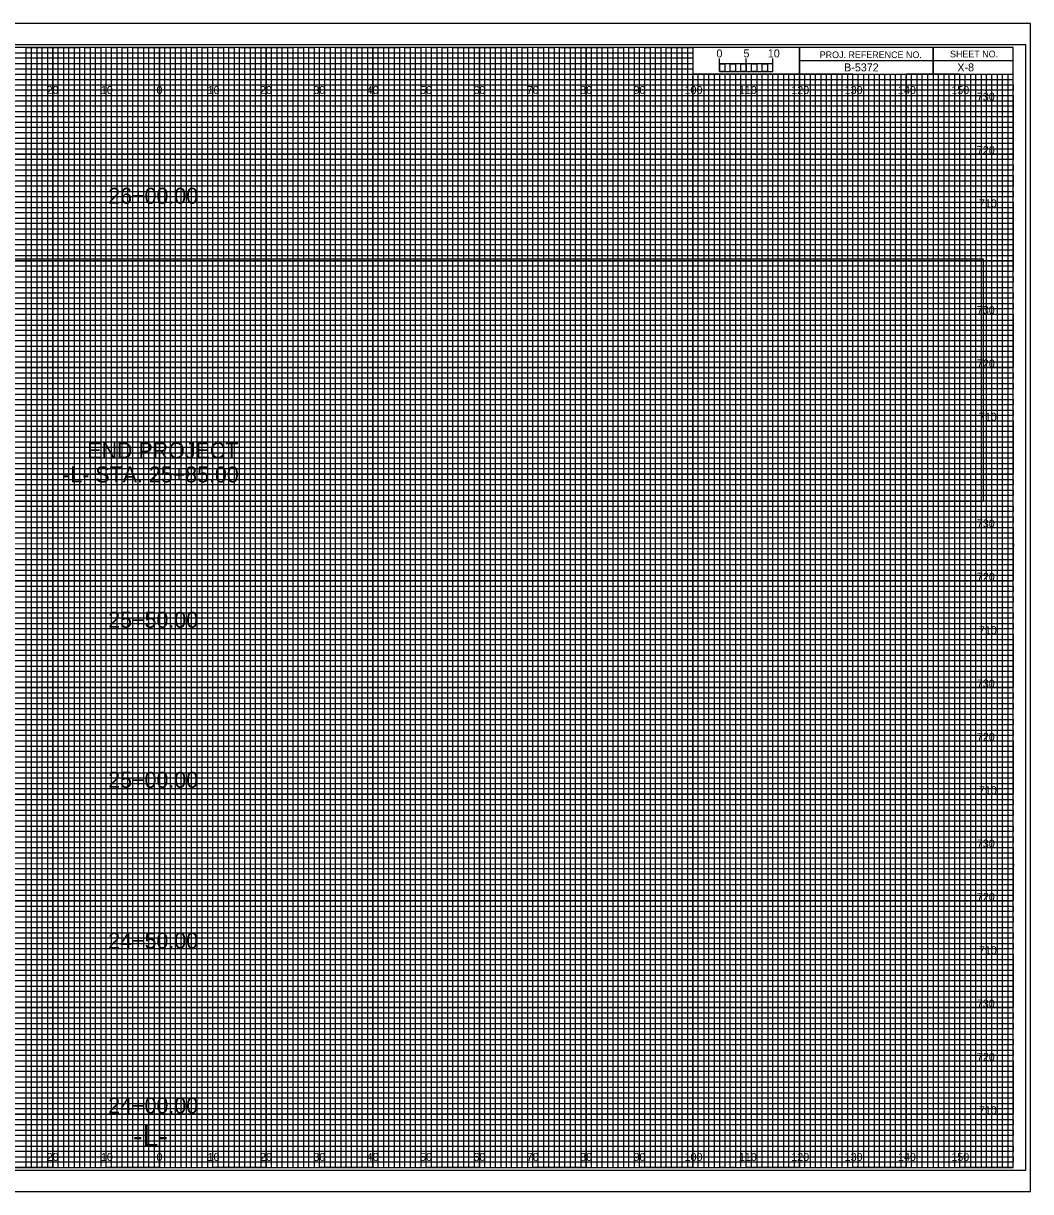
# Model space of a CAD drawing. Extents: x -98 to 717, y -10 to 1974.
# Drawn here: x 134.5 to 323.3, y 1535.5 to 1754.5 of the extents above; entities that cross this region are included whole.
import ezdxf

# ---------------------------------------------------------------- set-up
doc = ezdxf.new("R2010")
doc.units = 0
for name, color, linetype in [('Default', 7, 'Continuous'), ('Exist XS Center Line Elevation Label', 7, 'Continuous'), ('Prop CMT Conc Surface', 7, 'Continuous'), ('Prop CMT Concrete Structures', 7, 'Continuous'), ('Prop CMT Pvmt Course 1', 7, 'Continuous'), ('Prop CMT Pvmt Course 1 CG', 7, 'Continuous'), ('Prop CMT Pvmt Course 2', 7, 'Continuous'), ('Prop CMT Pvmt Course 3', 7, 'Continuous'), ('Prop CMT Pvmt Surface', 7, 'Continuous'), ('Prop CMT Pvmt Surface Shoulder', 7, 'Continuous'), ('Prop CMT Shld Paved Course 1', 7, 'Continuous'), ('Prop CMT Shld Paved Course 2', 7, 'Continuous'), ('Prop CMT Shld Paved Course 3', 7, 'Continuous'), ('Prop CMT Slope Grass', 7, 'Continuous'), ('Prop CMT Subgrade Earthwork', 7, 'Continuous'), ('Prop XS Ditch Standard Text', 7, 'Continuous'), ('Prop XS Earthwork Shape', 7, 'Continuous'), ('Prop XS Elevation Labels', 7, 'Continuous'), ('Typical Curb CELL', 7, 'Continuous')]:
    doc.layers.add(name, color=color, linetype=linetype)

msp = doc.modelspace()

# ---------------------------------------------------------------- linework, layer by layer
at = {"layer": 'Default'}
msp.add_lwpolyline([(-13.4, 1535.5), (323.3, 1535.5), (323.3, 1754.5), (-13.4, 1754.5)], close=True, dxfattribs=at)
at = {"layer": 'Exist XS Center Line Elevation Label'}
for p, q in [((0, 1749), (260, 1749)), ((260, 1747.98), (0, 1747.98)), ((260, 1749), (260, 1747.98)), ((0, 1747), (260, 1747)), ((260, 1745.89), (0, 1745.89)), ((260, 1747), (260, 1745.89)), ((0, 1744), (320, 1744))]:
    msp.add_line(p, q, dxfattribs=at)
for points in [[(0, 1743), (270, 1743), (320, 1743), (320, 1742), (0, 1742)], [(0, 1741), (320, 1741), (320, 1739), (0, 1739)], [(0, 1738), (320, 1738), (320, 1737), (0, 1736.98)], [(0, 1736), (320, 1736), (320, 1734), (0, 1734)], [(0, 1733), (320, 1733), (320, 1732), (0, 1732)], [(0, 1731), (320, 1731), (320, 1729), (0, 1729)], [(0, 1728), (320, 1728), (320, 1727), (0, 1727)], [(0, 1726), (320, 1726), (320, 1724), (0, 1724)], [(0, 1723), (320, 1723), (320, 1722), (0, 1722)], [(0, 1721), (320, 1721), (320, 1719), (0, 1719)], [(0, 1718), (320, 1718), (320, 1717), (0, 1717)], [(0, 1716), (320, 1716), (320, 1713.95), (320, 1713), (320, 1712), (0, 1712)], [(0, 1714), (320, 1714), (320, 1713), (0, 1713)], [(0, 1711), (320, 1711), (320, 1709), (0, 1709.03)], [(0, 1709.03), (320, 1709), (320, 1708), (0, 1708)], [(0, 1707), (320, 1707), (320, 1706), (0, 1706)], [(0, 1704), (320, 1704), (320, 1703), (0, 1703)], [(0, 1702), (320, 1702), (320, 1701), (0, 1701)], [(-0.07, 1698.89), (320, 1698.89), (320, 1697.88), (-0.07, 1697.88)], [(0, 1697), (320, 1697), (320, 1696), (0, 1696)], [(0, 1694), (320, 1694), (320, 1693), (0, 1693)], [(0, 1692), (320, 1692), (320, 1691), (0, 1691)], [(0, 1689), (320, 1689), (320, 1688), (0, 1688)], [(0, 1687), (320, 1687), (320, 1686), (0, 1686)], [(0, 1684), (320, 1684), (320, 1683), (0, 1683)], [(0, 1682), (320, 1682), (320, 1681), (0, 1681)], [(0, 1679), (320, 1679), (319.99, 1677.98), (0, 1678)], [(0, 1677), (320, 1677), (320, 1676), (0, 1676)], [(0, 1674), (320, 1674), (320, 1673), (0, 1673)], [(0, 1672), (320, 1672), (320, 1671), (0, 1671)], [(0, 1669), (320, 1669), (320, 1668), (0, 1668)], [(0, 1667), (320, 1667), (320, 1666), (0, 1666)], [(0, 1664), (320, 1664), (320, 1663), (0, 1663)], [(0, 1662), (320, 1662), (320, 1661), (0, 1661)], [(0, 1659), (320, 1659), (320, 1658), (0, 1658)], [(0, 1656.99), (320.07, 1656.91), (320, 1656), (0, 1656)], [(0, 1654), (320, 1654), (320, 1653), (0, 1653)], [(0, 1652), (320, 1652), (320, 1651), (0, 1651)], [(0, 1649), (320, 1649), (320, 1648), (0, 1648)], [(0, 1647), (320, 1647), (320, 1646), (0, 1646)], [(0, 1644), (320, 1644), (320, 1643), (0, 1643)], [(0, 1642), (320, 1642), (320, 1641), (0, 1641)], [(0, 1639), (320, 1639), (320, 1638), (0, 1638)], [(0, 1637), (320, 1637), (320, 1636), (0, 1636)], [(0, 1634), (320, 1634), (320, 1633), (0, 1633)], [(0, 1632), (320, 1632), (320, 1631), (0, 1631)], [(0, 1629), (320, 1629), (320, 1628), (0, 1628)], [(0, 1627), (320, 1627), (320, 1626), (0, 1626)], [(0, 1624), (320, 1624), (320, 1623), (0, 1623)], [(0, 1622), (320, 1622), (320, 1621), (0, 1621)], [(0, 1619), (320, 1619), (319.99, 1617.98), (0, 1618)], [(0, 1617), (320, 1617), (320, 1616), (0, 1616)], [(0, 1614), (320, 1614), (320, 1613), (0, 1613)], [(0, 1612), (320, 1612), (320, 1611), (0, 1611)], [(0, 1609), (320, 1609), (320, 1608), (0, 1608)], [(0, 1607), (320, 1607), (320, 1606), (0, 1606)], [(0, 1604), (320, 1604), (320, 1603), (0, 1603)], [(0, 1602), (320, 1602), (320, 1601), (0, 1601)], [(0, 1599), (320, 1599), (320, 1598), (0, 1598)], [(0, 1596.99), (320.07, 1596.91), (320, 1596), (0, 1596)], [(0, 1594), (320, 1594), (320, 1593), (0, 1593)], [(0, 1592), (320, 1592), (320, 1591), (0, 1591)], [(0, 1589), (320, 1589), (320, 1588), (0, 1588)], [(0, 1587), (320, 1587), (320, 1586), (0, 1586)], [(0, 1584), (320, 1584), (320, 1583), (0, 1583)], [(0, 1582), (320, 1582), (320, 1581), (0, 1581)], [(0, 1579), (320, 1579), (320, 1578), (0, 1578)], [(0, 1577), (320, 1577), (320, 1576), (0, 1576)], [(0, 1574), (320, 1574), (320, 1573), (0, 1573)], [(0, 1572), (320, 1572), (320, 1571), (0, 1571)], [(0, 1569), (320, 1569), (320, 1568), (0, 1568)], [(0, 1567), (320, 1567), (320, 1566), (0, 1566)], [(0, 1564), (320, 1564), (320, 1563), (0, 1563)], [(0, 1562), (320, 1562), (320, 1561), (0, 1561)], [(0, 1559), (320, 1559), (320, 1558), (0, 1558)], [(0, 1557), (320, 1557), (320, 1556), (0, 1556)], [(0, 1554), (320, 1554), (320, 1553), (0, 1553)], [(0, 1552), (320, 1552), (320, 1551), (0, 1551)], [(0, 1549), (320, 1549), (320, 1548), (0, 1548)], [(0, 1547), (320, 1547), (320, 1546), (0, 1546)], [(0, 1544), (320, 1544), (320, 1543), (0, 1543)], [(0, 1542), (320, 1542), (320, 1541), (0, 1541)]]:
    msp.add_lwpolyline(points, dxfattribs=at)
at = {"layer": 'Prop CMT Conc Surface'}
for p, q in [((305, 1750), (305, 1745)), ((305, 1745), (305, 1750)), ((280, 1747.5), (280, 1745)), ((320, 1747.49), (280, 1747.49)), ((280, 1745), (320, 1745))]:
    msp.add_line(p, q, dxfattribs=at)
for points in [[(320, 1750), (0, 1750), (0, 1540), (320, 1540)], [(280, 1750), (260, 1750), (260, 1745.03), (280, 1745.03)], [(320, 1750), (280, 1750), (280, 1745), (320, 1745)]]:
    msp.add_lwpolyline(points, close=True, dxfattribs=at)
at = {"layer": 'Prop CMT Concrete Structures'}
for p, q in [((140, 1540), (140, 1750)), ((150, 1540), (150, 1750)), ((160, 1540), (160, 1750)), ((170, 1540), (170, 1750)), ((180, 1540), (180, 1750)), ((190, 1540), (190, 1750)), ((200, 1540), (200, 1750)), ((210, 1540), (210, 1750)), ((220, 1540), (220, 1750)), ((230, 1540), (230, 1750)), ((240, 1540), (240, 1750)), ((250, 1540), (250, 1750)), ((260, 1540), (260, 1744.69)), ((270, 1540), (270, 1744.69)), ((280, 1540), (280, 1744.69)), ((290, 1540), (290, 1744.69)), ((300, 1540), (300, 1744.69)), ((310, 1540), (310, 1744.69)), ((0, 1740), (320, 1740)), ((0, 1730), (320, 1730)), ((0, 1720), (320, 1720)), ((0, 1710), (320, 1710)), ((0, 1700), (320, 1700)), ((0, 1690), (320, 1690)), ((0, 1680), (320, 1680)), ((0, 1670), (320, 1670)), ((0, 1660), (320, 1660)), ((0, 1650), (320, 1650)), ((0, 1640), (320, 1640)), ((0, 1630), (320, 1630)), ((0, 1620), (320, 1620)), ((0, 1610), (320, 1610)), ((0, 1600), (320, 1600)), ((0, 1590), (320, 1590)), ((0, 1580), (320, 1580)), ((0, 1570), (320, 1570)), ((0, 1560), (320, 1560)), ((0, 1550), (320, 1550))]:
    msp.add_line(p, q, dxfattribs=at)
at = {"layer": 'Prop CMT Pvmt Course 2'}
msp.add_lwpolyline([(-13.4, 1535.5), (323.3, 1535.5), (323.3, 1754.5), (-13.4, 1754.5)], close=True, dxfattribs=at)
at = {"layer": 'Prop CMT Pvmt Course 3'}
msp.add_lwpolyline([(-10.8, 1539.5), (322.4, 1539.5), (322.4, 1750.5), (-10.8, 1750.5)], close=True, dxfattribs=at)
at = {"layer": 'Prop CMT Pvmt Surface'}
for p, q in [((323.3, 1754.5), (-13.4, 1754.5)), ((-13.4, 1535.5), (323.3, 1535.5))]:
    msp.add_line(p, q, dxfattribs=at)
at = {"layer": 'Prop CMT Slope Grass'}
for p, q in [((265, 1745.49), (265, 1747.9)), ((265, 1746.9), (265, 1747.9)), ((270, 1745.49), (270, 1747.9)), ((275, 1745.49), (275, 1747.9)), ((275, 1746.9), (275, 1747.9))]:
    msp.add_line(p, q, dxfattribs=at)
for points in [[(275, 1746.9), (265, 1746.9), (265, 1745.49), (275, 1745.49)], [(265, 1746.9), (266, 1746.9), (266, 1745.49), (265, 1745.49)], [(267, 1746.9), (268, 1746.9), (268, 1745.49), (267, 1745.49)], [(269, 1746.9), (270, 1746.9), (270, 1745.49), (269, 1745.49)], [(271, 1746.9), (272, 1746.9), (272, 1745.49), (271, 1745.49)], [(273, 1746.9), (274, 1746.9), (274, 1745.49), (273, 1745.49)]]:
    msp.add_lwpolyline(points, close=True, dxfattribs=at)
at = {"layer": 'Prop CMT Subgrade Earthwork'}
for p, q in [((267, 1745), (266.01, 1745)), ((266.01, 1745), (266.01, 1540)), ((267, 1540), (267, 1745)), ((269, 1745), (268, 1745)), ((268, 1745), (268, 1540)), ((269, 1540), (269, 1745)), ((266.01, 1540), (265, 1540)), ((268, 1540), (267, 1540))]:
    msp.add_line(p, q, dxfattribs=at)
for points in [[(135, 1540), (136, 1540), (136, 1750), (137, 1750), (137, 1540)], [(137, 1540), (138, 1540), (138, 1750), (139, 1750), (139, 1540)], [(140, 1540), (141, 1540), (141, 1750), (142, 1750), (142, 1540)], [(142, 1540), (143, 1540), (143, 1750), (144, 1750), (144, 1540)], [(145, 1540), (146, 1540), (146, 1750), (147, 1750), (147, 1540)], [(147, 1540), (148, 1540), (148, 1750), (149, 1750), (149, 1540)], [(150, 1540), (151, 1540), (151, 1750), (152, 1750), (152, 1540)], [(152, 1540), (153, 1540), (153, 1750), (154, 1750), (154, 1540)], [(155, 1540), (156, 1540), (156, 1750), (157, 1750), (157, 1540)], [(157, 1540), (158, 1540), (158, 1750), (159, 1750), (159, 1540)], [(160, 1540), (161, 1540), (161, 1750), (162, 1750), (162, 1540)], [(162, 1540), (163, 1540), (163, 1750), (164, 1750), (164, 1540)], [(165, 1540), (166, 1540), (166, 1750), (167, 1750), (167, 1540)], [(167, 1540), (168, 1540), (168, 1750), (169, 1750), (169, 1540)], [(170, 1540), (171, 1540), (171, 1750), (172, 1750), (172, 1540)], [(172, 1540), (173, 1540), (173, 1750), (174, 1750), (174, 1540)], [(175, 1540), (176, 1540), (176, 1750), (177, 1750), (177, 1540)], [(177, 1540), (178, 1540), (178, 1750), (179, 1750), (179, 1540)], [(180, 1540), (181, 1540), (181, 1750), (182, 1750), (182, 1540)], [(182, 1540), (183, 1540), (183, 1750), (184, 1750), (184, 1540)], [(185, 1540), (186, 1540), (186, 1750), (187, 1750), (187, 1540)], [(187, 1540), (188, 1540), (188, 1750), (189, 1750), (189, 1540)], [(190, 1540), (191, 1540), (191, 1750), (192, 1750), (192, 1540)], [(192, 1540), (193, 1540), (193, 1750), (194, 1750), (194, 1540)], [(195, 1540), (196, 1540), (196, 1750), (197, 1750), (197, 1540)], [(197, 1540), (198, 1540), (198, 1750), (199, 1750), (199, 1540)], [(200, 1540), (201, 1540), (201, 1750), (202, 1750), (202, 1540)], [(202, 1540), (203, 1540), (203, 1750), (204, 1750), (204, 1540)], [(205, 1540), (206, 1540), (206, 1750), (207, 1750), (207, 1540)], [(207, 1540), (208, 1540), (208, 1750), (209, 1750), (209, 1540)], [(210, 1540), (211, 1540), (211, 1750), (212, 1750), (212, 1540)], [(212, 1540), (213, 1540), (213, 1750), (214, 1750), (214, 1540)], [(215, 1540), (216, 1540), (216, 1750), (217, 1750), (217, 1540)], [(217, 1540), (218, 1540), (218, 1750), (219, 1750), (219, 1540)], [(220, 1540), (221, 1540), (221, 1750), (222, 1750), (222, 1540)], [(222, 1540), (223, 1540), (223, 1750), (224, 1750), (224, 1540)], [(225, 1540), (226, 1540), (226, 1750), (227, 1750), (227, 1540)], [(227, 1540), (228, 1540), (228, 1750), (229, 1750), (229, 1540)], [(230, 1540), (231, 1540), (231, 1750), (232, 1750), (232, 1540)], [(232, 1540), (233, 1540), (233, 1750), (234, 1750), (234, 1540)], [(235, 1540), (236, 1540), (236, 1750), (237, 1750), (237, 1540)], [(237, 1540), (238, 1540), (238, 1750), (239, 1750), (239, 1540)], [(240, 1540), (241, 1540), (241, 1750), (242, 1750), (242, 1540)], [(242, 1540), (243, 1540), (243, 1750), (244, 1750), (244, 1540)], [(245, 1540), (246, 1540), (246, 1750), (247, 1750), (247, 1540)], [(247, 1540), (248, 1540), (248, 1750), (249, 1750), (249, 1540)], [(250, 1540), (251, 1540), (251, 1750), (252, 1750), (252, 1540)], [(252, 1540), (253, 1540), (253, 1750), (254, 1750), (254, 1540)], [(255, 1540), (256, 1540), (256, 1750), (257, 1750), (257, 1540)], [(257, 1540), (258, 1540), (258, 1750), (259, 1750), (259, 1540)], [(260, 1540), (261, 1540), (261, 1745), (262.02, 1745), (262.02, 1540)], [(262, 1540), (263, 1540), (263, 1745), (263.99, 1745), (263.99, 1540)], [(270, 1540), (270.98, 1540), (270.98, 1745), (272, 1745), (272, 1540)], [(272, 1540), (273, 1540), (273, 1745), (274.05, 1745), (274.05, 1540)], [(275, 1540), (276, 1540), (276, 1745), (277, 1745), (277, 1540)], [(277, 1540), (278, 1540), (278, 1745), (279, 1745), (279, 1540)], [(280, 1540), (281, 1540), (281, 1745), (282, 1745), (282, 1540)], [(282, 1540), (283, 1540), (283, 1745), (284, 1745), (284, 1540)], [(285, 1540), (286, 1540), (286, 1745), (287, 1745), (287, 1540)], [(287, 1540), (288, 1540), (288, 1745), (289, 1745), (289, 1540)], [(290, 1540), (291, 1540), (291, 1745), (292, 1745), (292, 1540)], [(292, 1540), (293, 1540), (293, 1745), (294, 1745), (294, 1540)], [(295, 1540), (296, 1540), (296, 1745), (297, 1745), (297, 1540)], [(297, 1540), (298, 1540), (298, 1745), (299, 1745), (299, 1540)], [(300, 1540), (301, 1540), (301, 1745), (302, 1745), (302, 1540)], [(302, 1540), (303, 1540), (303, 1745), (304, 1745), (304, 1540)], [(305, 1540), (306, 1540), (306, 1745), (307, 1745), (307, 1540)], [(307, 1540), (308, 1540), (308, 1745), (309, 1745), (309, 1540)], [(310, 1540), (311, 1540), (311, 1745), (312, 1745), (312, 1540)], [(312, 1540), (313, 1540), (313, 1745), (314, 1745), (314, 1540)], [(315, 1540), (316, 1540), (316, 1745), (317, 1745), (317, 1540)], [(317, 1540), (318, 1540), (318, 1745), (319, 1745), (319, 1540)]]:
    msp.add_lwpolyline(points, dxfattribs=at)
at = {"layer": 'Prop XS Ditch Standard Text'}
msp.add_lwpolyline([(2.72, 1710.38), (314.41, 1710.38), (314.41, 1664.86), (2.72, 1664.86)], close=True, dxfattribs=at)
at = {"layer": 'Prop XS Elevation Labels'}
for p, q in [((150, 1750), (140, 1750)), ((140, 1750), (140, 1540)), ((150, 1540), (150, 1750)), ((170, 1750), (160, 1750)), ((160, 1750), (160, 1540)), ((170, 1540), (170, 1750)), ((190, 1750), (180, 1750)), ((180, 1750), (180, 1540)), ((190, 1540), (190, 1750)), ((210, 1750), (200, 1750)), ((200, 1750), (200, 1540)), ((210, 1540), (210, 1750)), ((230, 1750), (220, 1750)), ((220, 1750), (220, 1540)), ((230, 1540), (230, 1750)), ((250, 1750), (240, 1750)), ((240, 1750), (240, 1540)), ((250, 1540), (250, 1750)), ((260, 1750), (260, 1540)), ((270, 1540), (270, 1745)), ((290, 1745), (280, 1745)), ((280, 1745), (280, 1540)), ((290, 1540), (290, 1745)), ((310, 1745), (300, 1745)), ((300, 1745), (300, 1540)), ((310, 1540), (310, 1745)), ((140, 1540), (130, 1540)), ((160, 1540), (150, 1540)), ((180, 1540), (170, 1540)), ((200, 1540), (190, 1540)), ((220, 1540), (210, 1540)), ((240, 1540), (230, 1540)), ((260, 1540), (250, 1540)), ((280, 1540), (270, 1540)), ((300, 1540), (290, 1540)), ((320, 1540), (310, 1540)), ((320, 1540), (320, 1540))]:
    msp.add_line(p, q, dxfattribs=at)
for points in [[(0, 1740), (320, 1740), (320, 1730), (0, 1730)], [(0, 1720), (320, 1720), (320, 1710), (0, 1710)], [(0, 1700), (320, 1700), (320, 1690), (0, 1690)], [(0, 1680), (320, 1680), (320, 1670), (0, 1670)], [(0, 1660), (320, 1660), (320, 1650), (0, 1650)], [(0, 1640), (320, 1640), (320, 1630), (0, 1630)], [(0, 1620), (320, 1620), (320, 1610), (0, 1610)], [(0, 1600), (320, 1600), (320, 1590), (0, 1590)], [(0, 1580), (320, 1580), (320, 1570), (0, 1570)], [(0, 1560), (320, 1560), (320, 1550), (0, 1550)]]:
    msp.add_lwpolyline(points, dxfattribs=at)
at = {"layer": 'Typical Curb CELL'}
for points in [[(125, 1540), (135, 1540), (135, 1750), (145, 1750), (145, 1540), (155, 1540), (155, 1750), (165, 1750), (165, 1540), (175, 1540), (175, 1750), (185, 1750), (185, 1540), (195, 1540), (195, 1750), (205, 1750), (205, 1540), (215, 1540), (215, 1750), (225, 1750), (225, 1540), (235, 1540), (235, 1750), (245, 1750), (245, 1540), (255, 1540), (255, 1750), (259.93, 1750), (260, 1750), (260, 1745), (264.99, 1745), (264.99, 1540), (275, 1540), (275, 1745), (285, 1745), (285, 1540), (295, 1540), (295, 1745), (305, 1745), (305, 1540), (315, 1540), (315, 1745)], [(0, 1745), (275, 1745)], [(0, 1725), (320, 1725), (320, 1735), (0, 1735)], [(0, 1705), (320, 1705), (320, 1715), (0, 1715)], [(0, 1685), (320, 1685), (320, 1695), (0, 1695)], [(0, 1665), (320, 1665), (320, 1675), (0, 1675)], [(0, 1645), (320, 1645), (320, 1655), (0, 1655)], [(0, 1625), (320, 1625), (320, 1635), (0, 1635)], [(0, 1605), (320, 1605), (320, 1615), (0, 1615)], [(0, 1585), (320, 1585), (320, 1595), (0, 1595)], [(0, 1565), (320, 1565), (320, 1575), (0, 1575)], [(0, 1545), (320, 1545), (320, 1555), (0, 1555)]]:
    msp.add_lwpolyline(points, dxfattribs=at)

# ---------------------------------------------------------------- texts
at = {"layer": 'Prop CMT Conc Surface'}
for s, p in [('PROJ. REFERENCE NO.', (283.77, 1747.99)), ('SHEET NO.', (308.19, 1748.12))]:
    msp.add_text(s, height=1.25, dxfattribs=at).set_placement(p)
at = {"layer": 'Prop CMT Pvmt Course 1'}
for s, p in [('26+00.00', (150.41, 1720.69)), ('END PROJECT ', (146.49, 1672.94)), ('-L- STA. 25+85.00', (141.98, 1668.44)), ('25+50.00', (150.41, 1641.2)), ('25+00.00', (150.41, 1611.2)), ('24+50.00', (150.41, 1581.06)), ('24+00.00', (150.41, 1550.16))]:
    msp.add_text(s, height=3, dxfattribs=at).set_placement(p)
at = {"layer": 'Prop CMT Pvmt Course 1 CG'}
for s, p in [('730', (313.22, 1740)), ('720', (313.23, 1730)), ('710', (313.61, 1720)), ('730', (313.22, 1700)), ('720', (313.23, 1690)), ('710', (313.61, 1680)), ('730', (313.22, 1660)), ('720', (313.23, 1650)), ('710', (313.61, 1640)), ('730', (313.22, 1630)), ('720', (313.23, 1620)), ('710', (313.61, 1610)), ('730', (313.22, 1600)), ('720', (313.23, 1590)), ('710', (313.61, 1580)), ('730', (313.22, 1570)), ('720', (313.23, 1560)), ('710', (313.61, 1550))]:
    msp.add_text(s, height=1.5, dxfattribs=at).set_placement(p)
at = {"layer": 'Prop CMT Pvmt Surface Shoulder'}
for s, p in [('5', (269.47, 1748.12)), ('10', (274.04, 1748.12))]:
    msp.add_text(s, height=1.5, dxfattribs=at).set_placement(p)
at = {"layer": 'Prop CMT Shld Paved Course 1'}
msp.add_text('X-8', height=1.5, dxfattribs=at).set_placement((309.57, 1745.5))
at = {"layer": 'Prop CMT Shld Paved Course 2'}
msp.add_text('B-5372', height=1.5, dxfattribs=at).set_placement((288.34, 1745.5))
at = {"layer": 'Prop CMT Shld Paved Course 3'}
msp.add_text('-L-', height=4, dxfattribs=at).set_placement((155.06, 1544))
at = {"layer": 'Prop CMT Slope Grass'}
msp.add_text('0', height=1.5, dxfattribs=at).set_placement((264.41, 1748.12))
at = {"layer": 'Prop XS Earthwork Shape'}
for s, p in [('20', (138.86, 1741.25)), ('10', (149.04, 1741.25)), ('0', (159.45, 1741.25)), ('0', (159.45, 1741.25)), ('10', (169.04, 1741.25)), ('20', (178.86, 1741.25)), ('30', (188.86, 1741.25)), ('40', (198.86, 1741.25)), ('50', (208.86, 1741.25)), ('60', (218.86, 1741.25)), ('70', (228.86, 1741.25)), ('80', (238.86, 1741.25)), ('90', (248.86, 1741.25)), ('100', (258.44, 1741.25)), ('110', (268.62, 1741.25)), ('120', (278.44, 1741.25)), ('130', (288.44, 1741.25)), ('140', (298.44, 1741.25)), ('150', (308.44, 1741.25)), ('20', (138.86, 1541.25)), ('10', (149.04, 1541.25)), ('0', (159.45, 1541.25)), ('0', (159.45, 1541.25)), ('10', (169.04, 1541.25)), ('20', (178.86, 1541.25)), ('30', (188.86, 1541.25)), ('40', (198.86, 1541.25)), ('50', (208.86, 1541.25)), ('60', (218.86, 1541.25)), ('70', (228.86, 1541.25)), ('80', (238.86, 1541.25)), ('90', (248.86, 1541.25)), ('100', (258.44, 1541.25)), ('110', (268.62, 1541.25)), ('120', (278.44, 1541.25)), ('130', (288.44, 1541.25)), ('140', (298.44, 1541.25)), ('150', (308.44, 1541.25))]:
    msp.add_text(s, height=1.5, dxfattribs=at).set_placement(p)

doc.saveas('drawing.dxf')
